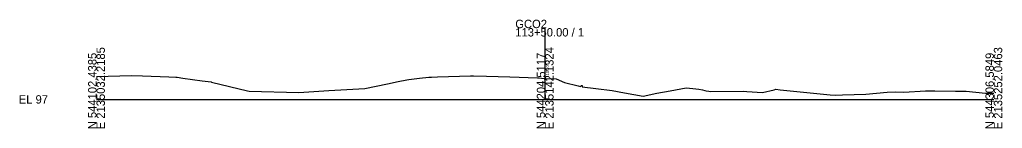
# Model space of a CAD drawing. Extents: x -14327 to 8886, y -10 to 39048.
# Drawn here: x 4974.3 to 5302.8, y 6990.3 to 7026.7 of the extents above; entities that cross this region are included whole.
import ezdxf

# ---------------------------------------------------------------- set-up
doc = ezdxf.new("R2010")
doc.units = 0
for name, color, linetype in [('RD_GPK_XS_Cell', 7, 'Continuous'), ('RD_XS_ExGround', 7, 'Continuous'), ('RD_XS_TX_Elev_EX', 7, 'Continuous')]:
    doc.layers.add(name, color=color, linetype=linetype)

msp = doc.modelspace()

# ---------------------------------------------------------------- linework, layer by layer
at = {"layer": 'RD_GPK_XS_Cell'}
for p, q in [((5150, 7000), (5150, 7023.85)), ((5000, 7000), (5150, 7000)), ((5150, 7000), (5300, 7000))]:
    msp.add_line(p, q, dxfattribs=at)
at = {"layer": 'RD_XS_ExGround'}
for p, q in [((5000, 7007.65), (5011.67, 7007.95)), ((5000, 7007.65), (5000, 7007.65)), ((5011.67, 7007.95), (5015.35, 7007.83)), ((5015.35, 7007.83), (5024.14, 7007.55)), ((5113.97, 7007.53), (5125.02, 7007.88)), ((5125.02, 7007.88), (5126.09, 7007.91)), ((5126.09, 7007.91), (5130.38, 7007.8)), ((5130.38, 7007.8), (5138.18, 7007.6)), ((5024.14, 7007.55), (5026.53, 7007.44)), ((5026.53, 7007.44), (5027.01, 7007.42)), ((5027.01, 7007.42), (5028.81, 7007.16)), ((5028.81, 7007.16), (5035.35, 7006.25)), ((5035.35, 7006.25), (5038.28, 7005.84)), ((5038.28, 7005.84), (5038.39, 7005.8)), ((5038.39, 7005.8), (5050.46, 7002.82)), ((5089.75, 7003.66), (5097.33, 7005.24)), ((5097.33, 7005.24), (5100.89, 7005.98)), ((5100.89, 7005.98), (5103.79, 7006.56)), ((5103.79, 7006.56), (5104.45, 7006.71)), ((5104.45, 7006.71), (5108.01, 7007.1)), ((5108.01, 7007.1), (5111.1, 7007.43)), ((5111.1, 7007.43), (5111.98, 7007.46)), ((5111.98, 7007.46), (5113.97, 7007.53)), ((5138.18, 7007.6), (5147.48, 7007.21)), ((5147.48, 7007.21), (5147.98, 7007.19)), ((5147.98, 7007.19), (5148.81, 7007.05)), ((5148.81, 7007.05), (5150, 7007)), ((5150, 7007), (5153.7, 7006.86)), ((5153.7, 7006.86), (5156.51, 7005.71)), ((5156.51, 7005.71), (5161.02, 7004.54)), ((5161.02, 7004.54), (5161.82, 7004.35)), ((5161.82, 7004.35), (5162.12, 7004.63)), ((5162.12, 7004.63), (5162.35, 7004.63)), ((5162.35, 7004.63), (5162.37, 7004.16)), ((5050.46, 7002.82), (5051.01, 7002.8)), ((5051.01, 7002.8), (5067.67, 7002.26)), ((5067.67, 7002.26), (5077.65, 7002.94)), ((5077.65, 7002.94), (5089.75, 7003.66)), ((5162.37, 7004.16), (5166.89, 7003.61)), ((5166.89, 7003.61), (5172.41, 7002.95)), ((5172.41, 7002.95), (5176.55, 7002.21)), ((5176.55, 7002.21), (5182.81, 7001.08)), ((5182.81, 7001.08), (5187.31, 7002.09)), ((5187.31, 7002.09), (5191.82, 7002.88)), ((5191.82, 7002.88), (5197.17, 7003.83)), ((5197.17, 7003.83), (5199.39, 7003.7)), ((5199.39, 7003.7), (5201.35, 7003.37)), ((5201.35, 7003.37), (5202.57, 7003.17)), ((5202.57, 7003.17), (5203.37, 7003.02)), ((5203.37, 7003.02), (5203.86, 7002.92)), ((5203.86, 7002.92), (5204.71, 7002.73)), ((5204.71, 7002.73), (5205.28, 7002.61)), ((5205.28, 7002.61), (5216.23, 7002.7)), ((5216.23, 7002.7), (5217.43, 7002.66)), ((5217.43, 7002.66), (5222.65, 7002.27)), ((5222.65, 7002.27), (5226.54, 7003.25)), ((5226.54, 7003.25), (5227.13, 7003.39)), ((5227.13, 7003.39), (5228.58, 7003.21)), ((5228.58, 7003.21), (5245.28, 7001.54)), ((5245.28, 7001.54), (5247.15, 7001.42)), ((5247.15, 7001.42), (5249.35, 7001.55)), ((5249.35, 7001.55), (5257.15, 7001.76)), ((5257.15, 7001.76), (5264.34, 7002.46)), ((5264.34, 7002.46), (5267.16, 7002.49)), ((5267.16, 7002.49), (5269.96, 7002.43)), ((5269.96, 7002.43), (5277.17, 7002.91)), ((5277.17, 7002.91), (5280.31, 7002.86)), ((5280.31, 7002.86), (5287.18, 7002.79)), ((5287.18, 7002.79), (5290.69, 7002.71)), ((5290.69, 7002.71), (5297.18, 7002.09)), ((5297.18, 7002.09), (5300, 7002.14))]:
    msp.add_line(p, q, dxfattribs=at)

# ---------------------------------------------------------------- texts
at = {"layer": 'RD_GPK_XS_Cell'}
for s, p in [('GCO2', (5140, 7023.85)), ('113+50.00 / 1', (5140, 7021.05)), ('EL 97', (4974, 6998.6))]:
    msp.add_text(s, height=2.8, dxfattribs=at).set_placement(p)
for s, p in [('N 544102.4385', (5000, 6990)), ('E 2135032.2185', (5002.8, 6990)), ('N 544204.5117', (5150, 6990)), ('E 2135142.1324', (5152.8, 6990)), ('N 544306.5849', (5300, 6990)), ('E 2135252.0463', (5302.8, 6990))]:
    msp.add_text(s, height=2.8, rotation=90, dxfattribs=at).set_placement(p)
at = {"layer": 'RD_XS_TX_Elev_EX'}
msp.add_text('104.00', height=1, rotation=90, dxfattribs=at).set_placement((5151.25, 7008))

doc.saveas('drawing.dxf')
